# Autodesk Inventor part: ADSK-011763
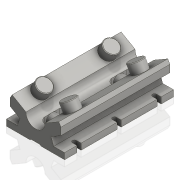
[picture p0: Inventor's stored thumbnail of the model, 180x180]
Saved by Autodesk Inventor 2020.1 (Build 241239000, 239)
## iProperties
Created: 1999-11
Part Number: ADSK-011763
Material: Aluminum
Document SubType Name: Modeling
Designer: tgregory
Density: 2.71 g/cm^3
Appearance: Steel
Mass: 1539.89 g
Surface Area: 878.77 cm^2
Volume: 568.223 cm^3
Control State: 0
Master: False
Checked Out: False
Shininess: 0.0
Length Units: 11269
Angle Units: 11279
Time Units: 11290
Mass Units: 11283
Length Display Precision: 3
Angle Display Precision: 2
Compacted: True
Dimensions: 101,6x65,1x190,5 mm
Mass: 1,54 kg
DocNumber: ADSK-011763.ipt
Folder: 01 - Themengebiete\Simplification\01 - Packaging machine\
VDS_Category: 3D Komponenten
Density: 0.0
Volumn: 0.0
Area: 0.0
PropertySet Name: Model Information
Author: tgregory
Revision Number: -
Title: guideline
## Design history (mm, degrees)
node "Extrusion6" dims "d92" = 190.5, "d93" = 0
node "Extrusion7" dims "d98" = 15.875, "d99" = 0
node "Extrusion13" dims "d155" = 3.175, "d156" = 0
  sketch "Sketch11"
    geometry: L1 (8, 168.822)-(0, 168.822); L2 (8, 161.678)-(0, 161.678); L3 (8, 98.822)-(0, 98.822); L4 (8, 91.678)-(0, 91.678); L5 (8, 28.822)-(0, 28.822); L6 (8, 21.678)-(0, 21.678); A1 r 3.572 centre (8, 165.25) between (8, 168.822) and (8, 161.678); A2 r 3.572 centre (8, 95.25) between (8, 98.822) and (8, 91.678); A3 r 3.572 centre (8, 25.25) between (8, 28.822) and (8, 21.678); 6 further points
    constraints: 12 end point, 6 point on circle, 6 tangent, 5 horizontal, 3 centre point, 3 coincident, 2 equal radius, 2 vertical alignment, 1 horizontal alignment, 1 parallel, 8 other
    dimensions: "d104" = 8 dimension on point (8, 95.25); "d154" = 7.14375 diameter of A1; "d164" = 140 distance of A1.centre point (8, 25.25); "d165" = 70 distance of point (8, 25.25) point (8, 95.25) (= 0.5 x d164)
node "Chamfer1" dims "d112" = 1.016, "d113" = 1.016, "d163" = 45 deg
node "Extrusion8" dims "d119" = 15.875, "d120" = 0
node "Extrusion12" dims "d152" = 3.175, "d153" = 0
node "Mirror11"
node "Extrusion9" dims "d128" = 15.875, "d129" = 0
node "Extrusion10" dims "d134" = 15.875, "d135" = 0
workplane "Work Plane7"
workplane "Work Plane8"
workplane "Work Plane9"
workaxis "Work Axis3"
workplane "Work Plane10"
workplane "Work Plane13"
workplane "Work Plane12"
workaxis "Work Axis4"
workplane "Work Plane14"
workplane "Work Plane15"
workplane "Arbeitsebene16"
node "Solide1"
node "Corps solides"
node "Corps surfaciques"
sketch "Sketch1" dims "d82" = 31.75
  geometry: L1 (7.086, -10.978)-(7.086, -0.209); L2 (7.086, -0.209)-(26.136, -0.209); L3 (26.136, -0.209)-(30.736, 12.429); L4 (30.736, 12.429)-(13.436, 22.417); L5 (13.436, 22.417)-(13.436, 35.117); L6 (17.118, 41.494)-(41.223, 27.576); L7 (7.086, -10.978)-(57.886, -10.978); L8 (57.886, 10.453)-(57.886, -10.978); L9 (13.436, 35.117)-(17.118, 41.494); L10 (29.17, 34.535)-(33.139, 41.409); L11 (-4.25, 54.109)-(83.828, 54.109); L12 (40.169, 28.185)-(44.138, 35.059); L13 (57.886, 27.122)-(15.472, 51.609); L14 (18.172, 40.885)-(22.141, 47.759); L15 (22.141, 47.759)-(26.109, 54.633); L16 (26.109, 54.633)-(48.106, 41.933); L17 (27.017, 54.109)-(26.383, 53.01); A1 r 16.669 centre (57.886, 27.122) between (41.223, 27.576) and (57.886, 10.453)
  constraints: 35 end point, 7 perpendicular, 7 point on line, 5 parallel, 2 equal length, 2 point on circle, 1 centre point, 1 coincident, 1 collinear, 1 midpoint, 1 vertical, 1 vertical alignment, 5 other
  dimensions: "d0" = 10.7696 distance from line of L2 L1.start; "d74" = 50.8 distance of L1.start L7.end; "d75" = 16.66875 radius of A1 (computed from d82); "d79" = 38.1 distance from line of A1.centre L7; "d81" = 50.8 distance from line of A1.centre L1 (= d74); "d83" = 44.45 distance from line of A1.centre L5; "d84" = 65.0875 distance between parallel lines of L11 L7; "d85" = 12.7 distance between parallel lines of L12 L10; "d86" = 12.7 distance between parallel lines of L10 L14 (= d85); "d87" = 7.9375 distance between parallel lines of L13 L6; "d88" = 30 deg angle of L7 L13; "d89" = 12.7 distance of L4.end L5.end; "d90" = 100 deg angle of L4 L3; "d91" = 19.05 distance of L1.end L2.end
sketch "Sketch10"
  geometry: L1 (-27.835, 0)-(0, 0) reference; L2 (0, 190.5)-(-27.835, 190.5) reference; L3 (-13.917, 190.5)-(-13.917, 0); C1 r 12.7 at (-13.917, 36.512); C2 r 12.7 at (-13.917, 153.987)
  constraints: 2 centre point, 2 end point, 2 midpoint, 2 point on line
  dimensions: "d94" = 36.5125 distance from line of C2.centre L2; "d95" = 36.5125 distance from line of L1 C1.centre (= d94); "d96" = 25.4 diameter of C2; "d97" = 25.4 diameter of C1 (= d96)
sketch "Sketch12"
  geometry: L1 (57.886, -10.978)-(7.086, -10.978) reference; L2 (57.886, 10.453)-(57.886, -10.978) reference; L3 (7.086, -0.209)-(26.136, -0.209) reference; L4 (57.886, -9.391)-(49.948, -9.391); L5 (49.948, -9.391)-(48.361, -10.978)
  constraints: 4 end point, 2 point on line, 1 parallel
  dimensions: "d116" = 7.9375 distance of L4.start L4.end; "d117" = 1.5875 distance between parallel lines of L1 L4; "d118" = 45 deg angle of L1 L5
sketch "Sketch13" dims "d156" = 0
  geometry: L1 (15.875, 0)-(0, 0) reference; L2 (15.875, 190.5)-(15.875, 0) reference; L3 (0, 190.5)-(15.875, 190.5) reference; L4 (0, 190.5)-(0, 0) reference; L5 (-19.255, 153.987)-(31.685, 153.987); L6 (-18.271, 36.512)-(34.146, 36.512); L7 (7.937, 190.5)-(7.937, 0); L8 (0, 166.687)-(0, 141.287); L9 (15.875, 166.687)-(15.875, 141.287); L10 (15.875, 49.212)-(15.875, 23.812); L11 (0, 23.812)-(0, 49.212); A1 r 7.938 centre (7.937, 166.687) between (0, 166.687) and (15.875, 166.687); A2 r 7.938 centre (7.938, 141.287) between (0, 141.287) and (15.875, 141.287); A3 r 7.938 centre (7.938, 49.212) between (15.875, 49.212) and (0, 49.212); A4 r 7.938 centre (7.938, 23.812) between (15.875, 23.812) and (0, 23.812)
  constraints: 14 end point, 12 point on line, 8 point on circle, 4 centre point, 3 equal radius, 2 midpoint, 2 parallel
  dimensions: "d121" = 15.875 diameter of A1; "d122" = 12.7 distance from line of A1.centre L5; "d123" = 12.7 distance from line of A2.centre L5 (= d122); "d124" = 12.7 distance from line of A3.centre L6 (= d122); "d125" = 12.7 distance from line of A4.centre L6 (= d122); "d126" = 36.5125 distance between parallel lines of L5 L3; "d127" = 36.5125 distance between parallel lines of L6 L1 (= d126)
sketch "Sketch14"
  geometry: L1 (0, 21.855)-(25.4, 21.855) reference; L2 (0, 0)-(25.4, 0) reference; L3 (117.475, 0)-(117.475, 21.855) reference; L4 (117.475, 21.855)-(142.875, 21.855) reference; L5 (142.875, 0)-(142.875, 21.855) reference; L6 (117.475, 0)-(142.875, 0) reference; L7 (12.7, 21.855)-(12.7, 0); L8 (130.175, 21.855)-(130.175, 0); C1 r 10.319 at (12.7, 11.906); C2 r 10.319 at (130.175, 11.906)
  constraints: 4 end point, 4 midpoint, 2 centre point, 2 point on line
  dimensions: "d130" = 11.90625 distance from line of C1.centre L2; "d131" = 11.90625 distance from line of C2.centre L6 (= d130); "d132" = 20.6375 diameter of C1; "d133" = 20.6375 diameter of C2 (= d132)
sketch "Sketch16"
  geometry: L1 (41.275, 190.5)-(0, 190.5) reference; L2 (0, 190.5)-(0, 0) reference; L3 (0, 0)-(41.275, 0) reference; L4 (22.225, 171.45)-(22.225, 19.05); L5 (28.575, 19.05)-(28.575, 171.45); A1 r 3.175 centre (25.4, 171.45) between (22.225, 171.45) and (28.575, 171.45); A2 r 3.175 centre (25.4, 19.05) between (22.225, 19.05) and (28.575, 19.05)
  constraints: 4 end point, 4 point on circle, 4 tangent, 2 centre point
  dimensions: "d146" = 6.35 diameter of A1; "d147" = 6.35 diameter of A2 (= d146); "d148" = 25.4 distance from line of A1.centre L2; "d149" = 25.4 distance from line of A2.centre L2 (= d148); "d150" = 19.05 distance from line of A1.centre L1; "d151" = 19.05 distance from line of A2.centre L3 (= d150)
other parameters: "d157" = -1.5875, "d158" = 3.57187 (= 0.5 x d154), "d159" = -1.5875, "d160" = 3.57187 (= 0.5 x d154), "d161" = 0, "d162" = 0
